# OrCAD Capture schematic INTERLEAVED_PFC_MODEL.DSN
size A
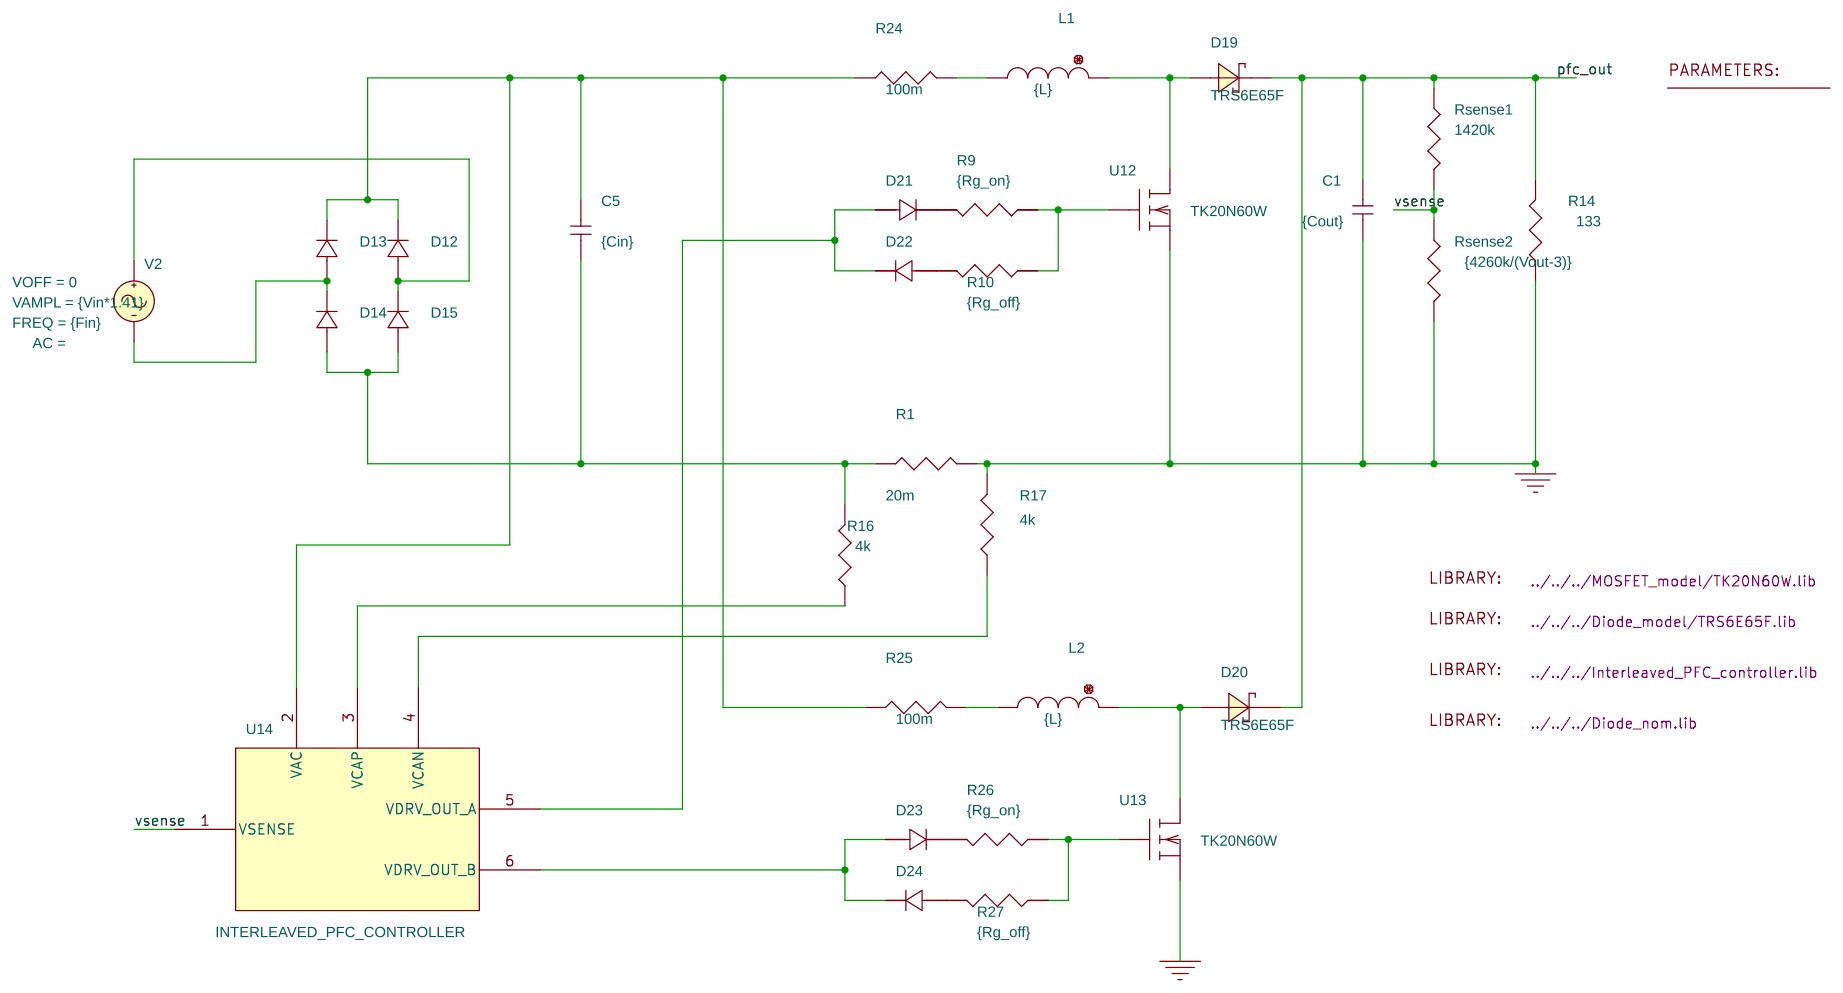
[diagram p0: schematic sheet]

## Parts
1  PARAM
C1  {Cout}  [RAD/CK05]
C5  {Cin}  [RAD/CK05]
D12  Dbreak
D13  Dbreak
D14  Dbreak
D15  Dbreak
D19  TRS6E65F
D20  TRS6E65F
D21  Diode_nom
D22  Diode_nom
D23  Diode_nom
D24  Diode_nom
L1  {L}  [DISC/.350x.175/LS.200x.100/.034]
L2  {L}  [DISC/.350x.175/LS.200x.100/.034]
LIB1  LIB
LIB2  LIB
LIB3  LIB
LIB4  LIB
R1  20m
R9  {Rg_on}
R10  {Rg_off}
R14  133
R16  4k
R17  4k
R24  100m
R25  100m
R26  {Rg_on}
R27  {Rg_off}
Rsense1  1420k
Rsense2  {4260k/(Vout-3)}
U12  TK20N60W
U13  TK20N60W
U14  INTERLEAVED_PFC_CONTROLLER
V2  VSIN

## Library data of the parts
1 = PARAM: Cin: 3.3u; Cout: 900u; Fc: 50k; Fin: 60; L: 180u; Rdrv_off: 0.5; Rdrv_on: 5; Rg_off: 10; Rg_on: 10; Vdrv_H: 12; Vin: 230; Vout: 400
C1 C5 = C
D12-D15 = Dbreak
D19 D20 = TRS6E65F
D21-D24 = Diode_nom
L1 L2 = L
LIB1 = LIB: FILENAME: ../../../MOSFET_model/TK20N60W.lib
LIB2 = LIB: FILENAME: ../../../Diode_model/TRS6E65F.lib
LIB3 = LIB: FILENAME: ../../../Interleaved_PFC_controller.lib
LIB4 = LIB: FILENAME: ../../../Diode_nom.lib
R1 R9 R10 R14 R16 R17 R24-R27 Rsense1 Rsense2 = R
U12 U13 = TK20N60W
U14 = INTERLEAVED_PFC_CONTROLLER
V2 = VSIN: FREQ: {Fin}; VAMPL: {Vin*1.41}; VOFF: 0

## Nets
0: C1.1 R1.2 R14.1 R17.2 Rsense2.2 U12.0(s) U13.0(s)
pfc_out: C1.2 D19.2 D20.2 R14.2 Rsense1.1
vsense: Rsense1.2 Rsense2.1 U14.1(VSENSE)
N2043033: C5.2 D12.1(2) D13.1(2) R24.1 R25.1 U14.2(VAC)
N2043069: L1.2 R24.2
N2043075: D19.1 L1.1 U12.2(d)
N2043153: D12.0(1) D15.1(2) V2.1(+)
N2043257: D21.0(1) D22.1(2) U14.5(VDRV_OUT_A)
N2043267: R9.1 R10.1 U12.1(g)
N2043481: C5.1 D14.0(1) D15.0(1) R1.1 R16.2
N2043531: D13.0(1) D14.1(2) V2.2(-)
N2043771: R17.1 U14.4(VCAN)
N2043783: R16.1 U14.3(VCAP)
N2043885: L2.2 R25.2
N2043891: D20.1 L2.1 U13.2(d)
N2044015: D23.0(1) D24.1(2) U14.6(VDRV_OUT_B)
N2044025: R26.1 R27.1 U13.1(g)
N2047296: D24.0(1) R27.2
N2047297: D21.1(2) R9.2
N2047298: D23.1(2) R26.2
N2047299: D22.0(1) R10.2
